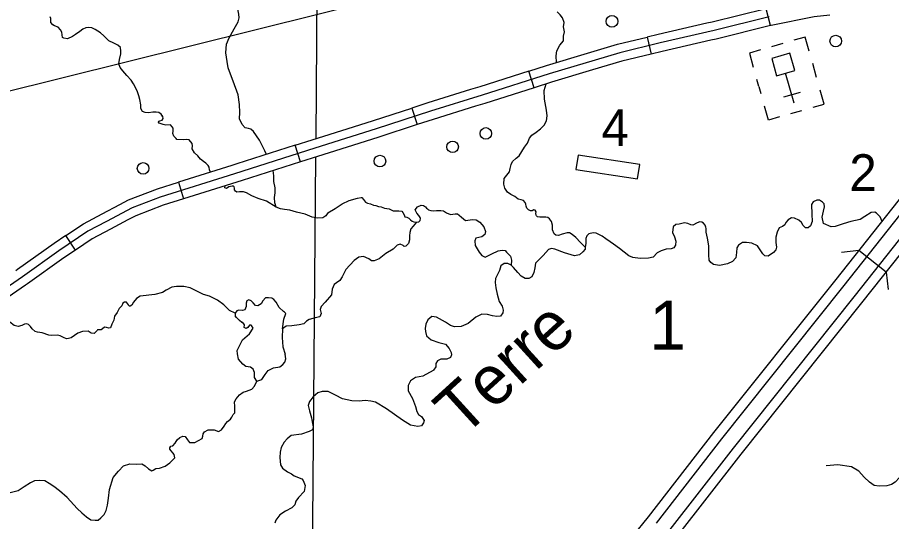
# Model space of a CAD drawing. Extents: x 1369979 to 1371646, y 379997 to 381064.
# Drawn here: x 1370824.5 to 1370912.7, y 380179.8 to 380230.7 of the extents above; entities that cross this region are included whole.
import ezdxf

# ---------------------------------------------------------------- set-up
doc = ezdxf.new("R2010")
doc.units = 0
doc.layers.add('Default', color=7, linetype='Continuous')
doc.layers.add('R_Border Notes', color=7, linetype='Continuous')

msp = doc.modelspace()

# ---------------------------------------------------------------- linework, layer by layer
at = {"layer": 'Default'}
msp.add_line((1370501.904, 380143.18), (1370944.13, 380253.288), dxfattribs=at)
at = {"layer": 'R_Border Notes'}
for p, q in [((1370900.49, 380229.875), (1370900.067, 380231.581)), ((1370888.035, 380228.71), (1370888.449, 380227.002)), ((1370901.732, 380228.069), (1370900.605, 380227.747)), ((1370905.156, 380224.641), (1370904.753, 380226.05)), ((1370876.618, 380223.598), (1370876.087, 380225.274)), ((1370876.087, 380225.274), (1370876.087, 380225.274)), ((1370899.324, 380223.724), (1370899.12, 380224.439)), ((1370902.892, 380222.033), (1370902.025, 380225.067)), ((1370899.324, 380223.724), (1370899.523, 380223.03)), ((1370903.495, 380223.12), (1370901.805, 380222.636)), ((1370864.28, 380221.553), (1370864.82, 380219.88)), ((1370902.538, 380220.987), (1370903.665, 380221.309)), ((1370853.027, 380216.123), (1370852.491, 380217.797)), ((1370852.491, 380217.797), (1370852.491, 380217.797)), ((1370881.076, 380216.81), (1370880.853, 380215.363)), ((1370887.302, 380215.852), (1370881.076, 380216.81)), ((1370887.079, 380214.404), (1370887.302, 380215.852)), ((1370880.853, 380215.363), (1370887.079, 380214.404)), ((1370840.7, 380214.064), (1370841.223, 380212.385)), ((1370830.32, 380207.22), (1370829.341, 380208.68)), ((1370909.425, 380207.161), (1370907.679, 380206.962)), ((1370912.177, 380204.972), (1370909.425, 380207.161)), ((1370912.177, 380204.972), (1370912.376, 380203.226))]:
    msp.add_line(p, q, dxfattribs=at)
for points in [[(1370854.696, 380233.431), (1370854.573, 380218.463)], [(1370846.052, 380224.718), (1370845.73, 380225.596), (1370845.641, 380226.262), (1370845.493, 380227.136), (1370845.552, 380228.01), (1370845.833, 380228.631), (1370846.351, 380229.535), (1370846.736, 380230.245), (1370846.825, 380230.66), (1370846.81, 380231.015), (1370846.691, 380231.519), (1370846.603, 380231.889), (1370846.573, 380232.2)], [(1370900.067, 380231.581), (1370894.617, 380230.231), (1370894.074, 380230.107)], [(1370900.364, 380230.749), (1370894.821, 380229.376), (1370889.356, 380228.126), (1370885.27, 380227.136), (1370878.131, 380225), (1370871.391, 380222.864), (1370866.16, 380221.235), (1370860.668, 380219.464), (1370854.474, 380217.51), (1370846.355, 380214.905), (1370838.872, 380212.573), (1370836.036, 380211.479), (1370833.433, 380210.099), (1370831.559, 380209.109), (1370828.644, 380207.155), (1370824.975, 380204.524), (1370820.447, 380201.413)], [(1370827.837, 380230.269), (1370827.812, 380230.588), (1370827.752, 380230.751)], [(1370878.895, 380226.146), (1370878.853, 380226.814), (1370878.927, 380227.332), (1370879.208, 380227.91), (1370879.578, 380228.354), (1370879.608, 380228.813), (1370879.697, 380229.243), (1370879.578, 380229.746), (1370879.652, 380230.19), (1370879.475, 380230.649), (1370879.268, 380230.946), (1370878.942, 380231.271)], [(1370906.477, 380230.944), (1370904.901, 380230.744), (1370900.555, 380229.891), (1370900.49, 380229.875)], [(1370836.177, 380223.998), (1370835.944, 380224.376), (1370835.515, 380224.835), (1370835.086, 380225.309), (1370834.819, 380225.649), (1370834.686, 380226.02), (1370834.745, 380226.464), (1370834.893, 380227.041), (1370834.908, 380227.293), (1370834.864, 380227.648), (1370834.583, 380227.915), (1370834.198, 380228.107), (1370833.665, 380228.344), (1370833.162, 380228.833), (1370832.852, 380229.159), (1370832.304, 380229.485), (1370831.964, 380229.633), (1370831.594, 380229.692), (1370831.358, 380229.647), (1370831.062, 380229.529), (1370830.751, 380229.277), (1370830.307, 380228.981), (1370829.997, 380228.759), (1370829.508, 380228.552), (1370829.153, 380228.596), (1370829.005, 380228.685), (1370828.961, 380228.937), (1370828.931, 380229.218), (1370828.798, 380229.455), (1370828.562, 380229.707), (1370828.192, 380229.84), (1370828.014, 380229.958), (1370827.837, 380230.181), (1370827.837, 380230.269)], [(1370894.074, 380230.107), (1370889.154, 380228.981), (1370888.035, 380228.71)], [(1370900.49, 380229.875), (1370895.025, 380228.521), (1370894.466, 380228.393)], [(1370882.02, 380227.081), (1370885.04, 380227.985), (1370888.035, 380228.71)], [(1370894.466, 380228.393), (1370889.557, 380227.27), (1370888.449, 380227.002)], [(1370904.394, 380227.307), (1370903.991, 380228.716), (1370902.864, 380228.393)], [(1370876.087, 380225.274), (1370877.872, 380225.84), (1370882.02, 380227.081)], [(1370899.484, 380227.427), (1370898.358, 380227.105), (1370898.76, 380225.696)], [(1370888.449, 380227.002), (1370885.499, 380226.287), (1370882.523, 380225.397)], [(1370882.523, 380225.397), (1370878.39, 380224.16), (1370876.618, 380223.598)], [(1370848.301, 380219.202), (1370848.005, 380219.431), (1370847.783, 380219.476), (1370847.443, 380219.565), (1370847.132, 380219.89), (1370846.866, 380220.468), (1370846.896, 380221.12), (1370846.866, 380221.904), (1370846.733, 380222.882), (1370846.245, 380224.259), (1370846.052, 380224.718)], [(1370876.087, 380225.274), (1370871.127, 380223.702), (1370870.191, 380223.411)], [(1370839.136, 380220.686), (1370838.974, 380220.933), (1370838.737, 380221.111), (1370838.456, 380221.141), (1370838.13, 380221.141), (1370837.701, 380221.066), (1370837.361, 380221.096), (1370837.095, 380221.2), (1370836.917, 380221.496), (1370836.902, 380221.866), (1370836.814, 380222.429), (1370836.725, 380222.799), (1370836.533, 380223.288), (1370836.177, 380223.998)], [(1370876.618, 380223.598), (1370871.654, 380222.025), (1370870.714, 380221.733)], [(1370877.951, 380220.771), (1370877.877, 380221.343), (1370877.729, 380222.068), (1370877.685, 380222.453), (1370877.685, 380222.764), (1370877.625, 380223.031), (1370877.625, 380223.327), (1370877.827, 380223.981)], [(1370870.191, 380223.411), (1370865.894, 380222.073), (1370864.28, 380221.553)], [(1370904.798, 380221.633), (1370905.924, 380221.955), (1370905.522, 380223.364)], [(1370858.393, 380219.668), (1370860.401, 380220.301), (1370864.28, 380221.553)], [(1370870.714, 380221.733), (1370866.425, 380220.398), (1370864.82, 380219.88)], [(1370901.418, 380220.667), (1370900.291, 380220.344), (1370899.888, 380221.753)], [(1370843.963, 380215.08), (1370843.841, 380215.326), (1370843.811, 380215.592), (1370843.722, 380215.755), (1370843.486, 380215.977), (1370843.234, 380216.17), (1370842.953, 380216.407), (1370842.657, 380216.732), (1370842.317, 380217.043), (1370842.095, 380217.428), (1370842.125, 380217.739), (1370842.095, 380217.991), (1370841.784, 380218.332), (1370841.518, 380218.391), (1370841.222, 380218.346), (1370840.556, 380218.391), (1370840.468, 380218.465), (1370840.246, 380218.716), (1370840.157, 380218.983), (1370840.187, 380219.22), (1370840.187, 380219.383), (1370840.172, 380219.516), (1370840.068, 380219.649), (1370839.891, 380219.871), (1370839.432, 380219.827), (1370839.151, 380219.886), (1370838.752, 380220.02), (1370838.692, 380220.138), (1370838.722, 380220.212), (1370838.84, 380220.271), (1370839.077, 380220.345), (1370839.151, 380220.493), (1370839.136, 380220.686), (1370839.047, 380220.73)], [(1370873.926, 380213.067), (1370873.675, 380213.471), (1370873.572, 380213.856), (1370873.587, 380214.448), (1370874.149, 380215.1), (1370874.208, 380215.455), (1370874.312, 380215.855), (1370874.445, 380216.151), (1370874.829, 380216.477), (1370875.11, 380216.729), (1370875.658, 380217.588), (1370875.969, 380218.002), (1370876.146, 380218.506), (1370876.398, 380218.831), (1370876.827, 380219.113), (1370877.27, 380219.453), (1370877.625, 380219.824), (1370877.877, 380220.268), (1370877.951, 380220.771)], [(1370849.59, 380216.866), (1370849.425, 380217.233), (1370848.893, 380218.313), (1370848.301, 380219.202)], [(1370852.491, 380217.797), (1370854.208, 380218.348), (1370858.393, 380219.668)], [(1370864.82, 380219.88), (1370860.935, 380218.627), (1370858.922, 380217.991)], [(1370852.491, 380217.797), (1370846.599, 380215.907)], [(1370858.922, 380217.991), (1370854.741, 380216.673), (1370853.027, 380216.123)], [(1370854.557, 380216.615), (1370854.188, 380171.633)], [(1370846.599, 380215.907), (1370846.09, 380215.743), (1370840.7, 380214.064)], [(1370853.027, 380216.123), (1370847.136, 380214.233)], [(1370850.594, 380211.536), (1370850.431, 380211.991), (1370850.417, 380212.539), (1370850.476, 380212.983), (1370850.491, 380213.249), (1370850.491, 380213.501), (1370850.343, 380214.123), (1370850.343, 380214.715), (1370850.264, 380215.236)], [(1370906.985, 380204.079), (1370916.068, 380215.547)], [(1370916.85, 380214.93), (1370907.764, 380203.458)], [(1370834.777, 380211.806), (1370835.67, 380212.28), (1370838.583, 380213.404), (1370840.7, 380214.064)], [(1370847.136, 380214.233), (1370846.62, 380214.067), (1370841.223, 380212.385)], [(1370908.955, 380202.508), (1370918.046, 380213.987)], [(1370850.594, 380211.536), (1370849.588, 380212.158), (1370848.774, 380212.439), (1370848.109, 380212.691), (1370847.591, 380212.987), (1370847.265, 380213.091), (1370846.881, 380213.091), (1370846.6, 380213.076), (1370846.467, 380213.165), (1370846.363, 380213.313), (1370846.378, 380213.476), (1370846.348, 380213.609), (1370846.245, 380213.654), (1370846.126, 380213.683), (1370845.801, 380213.609), (1370845.564, 380213.446), (1370845.401, 380213.505), (1370845.412, 380213.691)], [(1370881.791, 380207.496), (1370881.293, 380207.988), (1370880.834, 380208.491), (1370880.464, 380208.802), (1370880.213, 380208.95), (1370879.961, 380208.95), (1370879.473, 380208.832), (1370879.074, 380208.699), (1370878.822, 380208.728), (1370878.66, 380208.861), (1370878.482, 380209.246), (1370878.467, 380209.735), (1370878.393, 380210.105), (1370878.186, 380210.357), (1370877.994, 380210.505), (1370877.816, 380210.55), (1370877.298, 380210.535), (1370877.195, 380210.535), (1370876.958, 380210.564), (1370876.869, 380210.668), (1370876.825, 380210.742), (1370876.81, 380210.905), (1370876.825, 380211.083), (1370876.722, 380211.231), (1370876.588, 380211.275), (1370876.426, 380211.186), (1370876.263, 380211.186), (1370876.071, 380211.29), (1370875.893, 380211.453), (1370875.819, 380211.66), (1370875.804, 380211.867), (1370875.716, 380212.015), (1370875.538, 380212.208), (1370875.301, 380212.297), (1370875.02, 380212.371), (1370874.665, 380212.637), (1370874.266, 380212.83), (1370873.926, 380213.067)], [(1370909.733, 380201.886), (1370918.829, 380213.37)], [(1370841.223, 380212.385), (1370839.162, 380211.743), (1370836.401, 380210.678), (1370835.6, 380210.254)], [(1370855.782, 380210.959), (1370856.537, 380211.403), (1370857.232, 380211.877), (1370857.957, 380212.217), (1370858.785, 380212.469), (1370859.155, 380212.513), (1370859.244, 380212.513), (1370859.407, 380212.321), (1370859.584, 380212.054), (1370859.806, 380211.936), (1370860.087, 380211.891), (1370860.413, 380211.743), (1370860.635, 380211.729), (1370860.901, 380211.61), (1370861.197, 380211.566), (1370861.508, 380211.447), (1370861.981, 380211.373), (1370862.395, 380211.166), (1370862.972, 380211.181), (1370863.253, 380211.136), (1370863.372, 380211.003), (1370863.49, 380210.766), (1370863.564, 380210.588), (1370863.786, 380210.544), (1370863.963, 380210.425), (1370864.126, 380210.277), (1370864.318, 380210.129), (1370864.496, 380210.055), (1370864.747, 380210.026), (1370864.969, 380210.055), (1370865.132, 380210.189), (1370865.162, 380210.396), (1370865.102, 380210.514), (1370864.969, 380210.722), (1370864.792, 380210.929), (1370864.614, 380211.27), (1370864.836, 380211.595), (1370865.221, 380211.743), (1370865.458, 380211.714), (1370865.65, 380211.566), (1370865.768, 380211.432), (1370865.872, 380211.388), (1370865.961, 380211.27), (1370866.197, 380211.21), (1370866.463, 380211.181), (1370866.774, 380211.195), (1370867.218, 380211.225), (1370867.469, 380211.181), (1370867.765, 380210.959), (1370868.18, 380210.81), (1370868.431, 380210.855), (1370868.653, 380210.87), (1370868.875, 380210.885), (1370869.052, 380210.751), (1370869.289, 380210.544), (1370869.694, 380210.209)], [(1370905.962, 380211.579), (1370905.918, 380211.875), (1370905.755, 380212.067), (1370905.459, 380212.245), (1370905.178, 380212.245), (1370904.794, 380212.082), (1370904.646, 380211.801), (1370904.676, 380210.839), (1370904.691, 380210.114), (1370904.543, 380209.656), (1370904.292, 380209.478), (1370904.04, 380209.463), (1370903.804, 380209.7), (1370903.626, 380209.996), (1370903.346, 380210.247), (1370902.917, 380210.44), (1370902.621, 380210.455), (1370902.281, 380210.262), (1370902.03, 380209.996), (1370901.927, 380209.759), (1370901.69, 380209.611), (1370901.38, 380209.448), (1370901.158, 380209.019), (1370901.025, 380208.531), (1370901.04, 380207.969), (1370901.084, 380207.496)], [(1370829.341, 380208.68), (1370831.108, 380209.864), (1370833.022, 380210.875), (1370834.777, 380211.806)], [(1370855.782, 380210.959), (1370855.594, 380210.677), (1370855.299, 380210.485), (1370854.796, 380210.425), (1370854.204, 380210.544), (1370853.509, 380210.855), (1370852.636, 380211.047), (1370851.955, 380211.255), (1370851.423, 380211.329), (1370851.008, 380211.373), (1370850.594, 380211.536)], [(1370911.758, 380210.105), (1370911.564, 380210.558), (1370911.194, 380210.943), (1370911.017, 380211.046), (1370910.648, 380211.017), (1370910.027, 380210.602), (1370909.539, 380210.307), (1370908.608, 380210.114), (1370907.839, 380209.878), (1370907.041, 380209.582), (1370906.612, 380209.552), (1370905.858, 380209.907), (1370905.711, 380210.529), (1370905.839, 380211.15), (1370905.962, 380211.579)], [(1370869.694, 380210.209), (1370870.419, 380210.313), (1370870.774, 380210.268), (1370871.159, 380210.031), (1370871.558, 380209.572), (1370871.721, 380209.098), (1370871.647, 380208.802), (1370871.351, 380208.551), (1370870.745, 380208.402), (1370870.641, 380208.166), (1370870.686, 380207.692), (1370871.07, 380207.011), (1370871.337, 380206.67), (1370871.692, 380206.507), (1370872.343, 380206.833), (1370872.993, 380207.129), (1370873.408, 380207.203), (1370873.689, 380207.173), (1370873.822, 380207.011), (1370874.251, 380206.596), (1370874.34, 380206.196), (1370874.312, 380205.705)], [(1370835.6, 380210.254), (1370833.844, 380209.322), (1370832.01, 380208.353), (1370830.32, 380207.22)], [(1370864.747, 380210.026), (1370864.398, 380209.638), (1370864.176, 380209.357), (1370864.088, 380208.987), (1370864.028, 380208.646), (1370864.028, 380208.247), (1370863.925, 380207.876), (1370863.688, 380207.625), (1370863.511, 380207.58), (1370863.392, 380207.669), (1370863.096, 380207.817), (1370862.786, 380207.728), (1370862.401, 380207.314), (1370861.661, 380206.855), (1370860.966, 380206.322), (1370860.463, 380206.114), (1370860.197, 380206.144), (1370859.93, 380206.336), (1370859.413, 380206.559), (1370858.924, 380206.514), (1370858.466, 380206.174), (1370857.623, 380205.241), (1370857.253, 380204.515), (1370857.001, 380204.16), (1370856.661, 380203.908), (1370856.424, 380203.73), (1370856.247, 380203.286), (1370856.158, 380202.694), (1370855.537, 380201.953), (1370855.122, 380201.524), (1370855.019, 380201.213), (1370855.137, 380200.798), (1370854.975, 380200.487), (1370854.501, 380200.369), (1370853.895, 380200.221)], [(1370901.084, 380207.496), (1370901.044, 380207.229), (1370900.808, 380206.963), (1370900.246, 380206.608), (1370899.935, 380206.623), (1370899.729, 380206.845), (1370899.182, 380207.629), (1370898.605, 380207.925), (1370898.088, 380207.984), (1370897.674, 380207.969), (1370897.26, 380207.703), (1370897.112, 380207.436), (1370897.068, 380206.963), (1370897.009, 380206.445), (1370896.669, 380206.075), (1370896.166, 380205.838), (1370895.338, 380205.646), (1370894.747, 380205.765), (1370894.466, 380205.957), (1370894.289, 380206.208), (1370894.274, 380206.741), (1370894.259, 380207.658), (1370894.141, 380208.428), (1370894.008, 380209.034), (1370893.993, 380209.389), (1370893.964, 380209.522), (1370893.89, 380209.715), (1370893.742, 380209.922), (1370893.55, 380210.04), (1370893.358, 380210.055), (1370893.077, 380209.951), (1370892.663, 380209.744), (1370892.441, 380209.759), (1370892.131, 380209.907), (1370891.82, 380209.981), (1370891.259, 380209.848), (1370890.948, 380209.804), (1370890.653, 380209.567), (1370890.608, 380208.99), (1370890.786, 380208.561)], [(1370829.341, 380208.68), (1370828.144, 380207.877), (1370824.47, 380205.243), (1370824.276, 380205.11)], [(1370886.178, 380206.623), (1370885.232, 380207.377), (1370884.641, 380207.821), (1370884.301, 380208.058), (1370883.873, 380208.339), (1370883.503, 380208.635), (1370882.897, 380208.931), (1370882.572, 380208.96), (1370882.158, 380208.857), (1370881.951, 380208.664), (1370881.862, 380208.383), (1370881.833, 380207.865), (1370881.791, 380207.496), (1370881.777, 380207.318)], [(1370890.786, 380208.561), (1370890.923, 380208.102), (1370890.894, 380207.703), (1370890.746, 380207.436), (1370890.45, 380207.348), (1370889.962, 380207.303), (1370889.46, 380207.155), (1370889.046, 380206.933), (1370888.632, 380206.504), (1370888.174, 380206.386), (1370887.331, 380206.371), (1370886.592, 380206.475), (1370886.178, 380206.623)], [(1370830.32, 380207.22), (1370829.145, 380206.433), (1370825.48, 380203.804), (1370825.271, 380203.661)], [(1370881.777, 380207.318), (1370881.555, 380207.037), (1370881.215, 380206.741), (1370880.697, 380206.623), (1370879.707, 380206.933), (1370878.717, 380207.318), (1370878.392, 380207.377), (1370878.081, 380207.274), (1370877.534, 380206.667), (1370877.076, 380206.208), (1370876.78, 380205.883), (1370876.707, 380205.439), (1370876.588, 380204.966), (1370876.396, 380204.507), (1370876.086, 380204.359), (1370875.716, 380204.359), (1370875.332, 380204.596), (1370874.992, 380204.966), (1370874.548, 380205.469), (1370874.312, 380205.705), (1370873.957, 380205.868), (1370873.602, 380205.853), (1370873.277, 380205.631), (1370873.129, 380205.158), (1370872.73, 380204.359), (1370872.686, 380203.96), (1370872.775, 380203.412), (1370872.878, 380202.776)], [(1370825.271, 380203.661), (1370820.956, 380200.697), (1370820.212, 380200.149)], [(1370840.033, 380203.483), (1370839.462, 380203.157), (1370839.092, 380202.92), (1370838.322, 380202.743), (1370836.843, 380202.58), (1370836.458, 380202.328), (1370836.163, 380201.973), (1370836, 380201.647), (1370835.822, 380201.543), (1370835.734, 380201.558), (1370835.674, 380201.706), (1370835.467, 380201.943), (1370835.26, 380201.973), (1370835.083, 380201.854), (1370834.994, 380201.573), (1370834.728, 380201.306), (1370834.535, 380200.921), (1370834.269, 380200.551), (1370834.195, 380200.151), (1370833.988, 380199.737), (1370833.84, 380199.366), (1370833.677, 380199.337), (1370833.455, 380199.411), (1370833.233, 380199.44), (1370833.056, 380199.278), (1370832.923, 380199.159), (1370832.553, 380199.174), (1370832.509, 380199.085)], [(1370846.424, 380200.849), (1370845.862, 380201.114), (1370845.299, 380201.691), (1370844.648, 380202.165), (1370843.85, 380202.565), (1370843.228, 380202.743), (1370842.562, 380203.054), (1370841.897, 380203.409), (1370841.246, 380203.527), (1370840.506, 380203.542), (1370840.033, 380203.483)], [(1370894.769, 380188.788), (1370906.985, 380204.079)], [(1370907.764, 380203.458), (1370895.552, 380188.173)], [(1370849.516, 380202.389), (1370849.235, 380202.107), (1370849.057, 380201.782), (1370848.732, 380201.574), (1370848.495, 380201.619), (1370848.258, 380201.885), (1370848.066, 380202.093), (1370847.814, 380202.181), (1370847.607, 380202.107), (1370847.533, 380201.856), (1370847.563, 380201.53), (1370847.43, 380201.189), (1370847.193, 380201.13), (1370846.823, 380201.145), (1370846.616, 380201.086), (1370846.424, 380200.849), (1370846.424, 380200.572)], [(1370851.232, 380199.254), (1370851.35, 380200.242), (1370851.557, 380200.804), (1370851.424, 380200.938), (1370851.306, 380201.012), (1370850.891, 380201.411), (1370850.581, 380201.974), (1370850.344, 380202.211), (1370850.137, 380202.359), (1370849.811, 380202.389), (1370849.516, 380202.389)], [(1370872.878, 380202.776), (1370873.103, 380202.032), (1370873.398, 380201.558), (1370873.502, 380201.144), (1370873.458, 380200.878), (1370873.236, 380200.552), (1370872.852, 380200.508), (1370872.423, 380200.582), (1370871.905, 380200.715), (1370871.344, 380200.745), (1370870.738, 380200.449), (1370869.954, 380199.812), (1370869.26, 380199.517), (1370868.594, 380199.457), (1370868.181, 380199.62), (1370867.693, 380199.931), (1370866.762, 380200.449), (1370866.303, 380200.523), (1370865.904, 380200.182), (1370865.683, 380199.753), (1370865.638, 380199.309), (1370865.653, 380199.014), (1370865.771, 380198.555), (1370866.229, 380198.141), (1370867.013, 380197.889), (1370867.693, 380197.726), (1370868.062, 380197.297), (1370868.24, 380196.883), (1370868.284, 380196.632), (1370868.166, 380196.387), (1370867.811, 380196.217), (1370867.205, 380196.202), (1370866.88, 380196.025), (1370866.717, 380195.773), (1370866.702, 380195.433), (1370866.466, 380195.093), (1370866.422, 380195.048)], [(1370896.751, 380187.233), (1370908.955, 380202.508)], [(1370827.627, 380198.611), (1370826.936, 380198.878), (1370826.477, 380198.922), (1370826.24, 380198.996), (1370825.944, 380199.278), (1370825.767, 380199.515), (1370825.575, 380199.692), (1370825.397, 380199.766), (1370825.16, 380199.737), (1370824.879, 380199.589), (1370824.509, 380199.5), (1370824.125, 380199.589), (1370823.696, 380199.944), (1370823.311, 380200.329), (1370823.03, 380200.714), (1370822.616, 380201.129), (1370822.483, 380201.484), (1370822.429, 380201.709)], [(1370897.534, 380186.618), (1370909.733, 380201.886)], [(1370848.628, 380193.982), (1370848.406, 380194.353), (1370848.376, 380194.871), (1370848.258, 380195.197), (1370847.992, 380195.389), (1370847.518, 380195.463), (1370847.208, 380195.715), (1370846.764, 380196.218), (1370846.66, 380196.751), (1370846.646, 380197.092), (1370846.867, 380197.536), (1370847.163, 380198.173), (1370847.888, 380198.75), (1370848.243, 380199.328), (1370848.081, 380199.609), (1370848.066, 380199.624), (1370847.873, 380199.624), (1370847.726, 380199.402), (1370847.533, 380199.284), (1370847.356, 380199.387), (1370847.37, 380199.669), (1370847.223, 380199.891), (1370847.104, 380199.905), (1370846.882, 380200.098), (1370846.586, 380200.394), (1370846.424, 380200.572)], [(1370853.895, 380200.221), (1370853.643, 380200.054), (1370853.362, 380199.772), (1370852.889, 380199.669), (1370852.164, 380199.58), (1370851.587, 380199.52), (1370851.232, 380199.254)], [(1370832.509, 380199.085), (1370832.183, 380198.804), (1370831.902, 380198.819), (1370831.591, 380199.026), (1370831.029, 380199.011), (1370830.541, 380198.819), (1370829.89, 380198.374), (1370829.624, 380198.286), (1370829.417, 380198.241), (1370829.091, 380198.404), (1370828.78, 380198.552), (1370828.485, 380198.626), (1370827.922, 380198.582), (1370827.627, 380198.611)], [(1370851.232, 380199.254), (1370851.187, 380198.38), (1370851.261, 380197.462), (1370851.492, 380196.715)], [(1370848.628, 380193.982), (1370849.146, 380194.147), (1370849.456, 380194.665), (1370849.767, 380195.05), (1370850.314, 380195.331), (1370850.936, 380195.42), (1370851.261, 380195.672), (1370851.439, 380195.909), (1370851.557, 380196.235), (1370851.492, 380196.715)], [(1370866.422, 380195.048), (1370865.391, 380194.498), (1370864.652, 380194.365), (1370864.15, 380194.025), (1370863.898, 380193.536), (1370863.898, 380193.019), (1370864.357, 380192.22), (1370864.637, 380191.421), (1370864.77, 380190.918), (1370864.948, 380190.622), (1370865.258, 380190.429), (1370865.51, 380190.03), (1370865.465, 380189.764), (1370865.243, 380189.483), (1370864.889, 380189.409), (1370864.15, 380189.527), (1370863.351, 380190.045), (1370861.711, 380191.184), (1370860.602, 380191.865), (1370860.129, 380191.953), (1370859.567, 380192.027), (1370858.947, 380191.953), (1370858.208, 380191.998), (1370857.276, 380192.19), (1370856.567, 380192.575), (1370855.828, 380192.93)], [(1370840.334, 380186.247), (1370840.294, 380186.598), (1370840.146, 380186.761), (1370839.968, 380186.938), (1370839.85, 380187.131), (1370839.835, 380187.249), (1370839.953, 380187.427), (1370840.131, 380187.471), (1370840.368, 380187.723), (1370840.59, 380188.049), (1370840.856, 380188.301), (1370841.167, 380188.419), (1370841.374, 380188.389), (1370841.61, 380188.049), (1370841.817, 380187.797), (1370842.365, 380187.797), (1370843.105, 380188.182), (1370843.178, 380188.434), (1370843.208, 380188.656), (1370843.341, 380188.863), (1370843.711, 380189.056), (1370843.948, 380189.071), (1370844.332, 380189.071), (1370844.761, 380188.893), (1370845.072, 380189.071), (1370845.338, 380189.426), (1370845.501, 380189.707), (1370845.664, 380189.915), (1370845.975, 380190.152), (1370846.108, 380190.344), (1370846.226, 380190.625), (1370846.404, 380190.803), (1370846.404, 380191.114), (1370846.404, 380191.44), (1370846.374, 380191.899), (1370846.522, 380192.195), (1370846.892, 380192.61), (1370847.247, 380192.876), (1370847.587, 380192.965), (1370848.12, 380193.187), (1370848.386, 380193.483), (1370848.628, 380193.982)], [(1370855.828, 380192.93), (1370855.21, 380192.93), (1370854.796, 380192.811), (1370854.308, 380192.412), (1370853.939, 380191.939), (1370853.82, 380191.524), (1370853.939, 380190.992), (1370854.131, 380190.296), (1370854.22, 380189.867), (1370854.323, 380189.379), (1370854.249, 380189.083), (1370853.924, 380188.891), (1370853.126, 380188.624), (1370852.106, 380188.506), (1370851.677, 380188.166), (1370851.382, 380187.811), (1370851.071, 380187.278), (1370850.982, 380186.814), (1370850.953, 380186.287)], [(1370888.165, 380180.291), (1370894.769, 380188.788)], [(1370895.552, 380188.173), (1370888.941, 380179.667)], [(1370890.128, 380178.712), (1370896.751, 380187.233)], [(1370890.905, 380178.088), (1370897.534, 380186.618)], [(1370916.474, 380186.701), (1370915.367, 380186.248), (1370914.465, 380185.552), (1370913.976, 380184.723), (1370913.518, 380184.264), (1370913.074, 380183.79), (1370912.704, 380183.538), (1370912.245, 380183.419), (1370911.476, 380183.39), (1370910.973, 380183.464), (1370910.485, 380183.804), (1370909.967, 380184.278), (1370909.405, 380184.885), (1370908.665, 380185.344)], [(1370829.478, 380182.234), (1370830.469, 380181.138), (1370830.957, 380180.679), (1370831.431, 380180.294), (1370831.875, 380179.998), (1370832.289, 380179.969), (1370832.599, 380179.969), (1370832.866, 380180.191), (1370833.221, 380180.517), (1370833.428, 380180.931), (1370833.561, 380181.479), (1370833.635, 380182.175), (1370833.739, 380183.049), (1370834.123, 380184.248), (1370834.671, 380184.914), (1370835.174, 380185.433), (1370835.81, 380185.625), (1370836.517, 380185.595), (1370837.023, 380185.64)], [(1370837.023, 380185.64), (1370837.36, 380185.447), (1370837.686, 380185.122), (1370838.026, 380184.944), (1370838.159, 380184.988), (1370838.41, 380185.181), (1370838.795, 380185.196), (1370839.357, 380185.388), (1370839.845, 380185.729), (1370840.334, 380186.247)], [(1370850.953, 380186.287), (1370851.027, 380185.526), (1370851.219, 380185.186), (1370851.721, 380184.846), (1370852.121, 380184.624), (1370852.401, 380184.432)], [(1370908.665, 380185.344), (1370907.279, 380185.552), (1370906.11, 380185.433)], [(1370829.478, 380182.234), (1370828.703, 380182.908), (1370828.141, 380183.352), (1370827.652, 380183.663), (1370827.223, 380183.93), (1370826.661, 380183.959), (1370826.188, 380183.915), (1370825.774, 380183.707), (1370825.137, 380183.308), (1370824.516, 380182.908), (1370823.717, 380182.701), (1370822.889, 380182.686)], [(1370852.401, 380184.432), (1370853.155, 380184.121), (1370853.288, 380183.943), (1370853.51, 380183.455), (1370853.421, 380182.863), (1370852.83, 380182.242), (1370852.549, 380181.857), (1370852.446, 380181.517), (1370852.15, 380181.191), (1370851.515, 380180.851), (1370850.953, 380180.496), (1370850.539, 380179.963), (1370850.435, 380179.638)], [(1370880.257, 380170.534), (1370888.165, 380180.291)]]:
    msp.add_lwpolyline(points, dxfattribs=at)
msp.add_lwpolyline([(1370900.613, 380226.565), (1370901.116, 380224.807), (1370902.939, 380225.328), (1370902.437, 380227.086)], close=True, dxfattribs=at)
for centre in [(1370884.489, 380230.305), (1370907.079, 380228.318), (1370871.75, 380218.988), (1370868.398, 380217.635), (1370861.056, 380216.198), (1370837.143, 380215.462)]:
    msp.add_circle(centre, 0.586, dxfattribs=at)

# ---------------------------------------------------------------- texts
for s, height, p in [('4', 3.712, (1370883.427, 380217.716)), ('2', 3.712, (1370908.458, 380213.177)), ('1', 4.95, (1370888.265, 380197.164))]:
    msp.add_text(s, height=height, dxfattribs=at).set_placement(p)
msp.add_text('Terre', height=4.95, rotation=42.30004, dxfattribs=at).set_placement((1370869.427, 380188.229))

doc.saveas('drawing.dxf')
